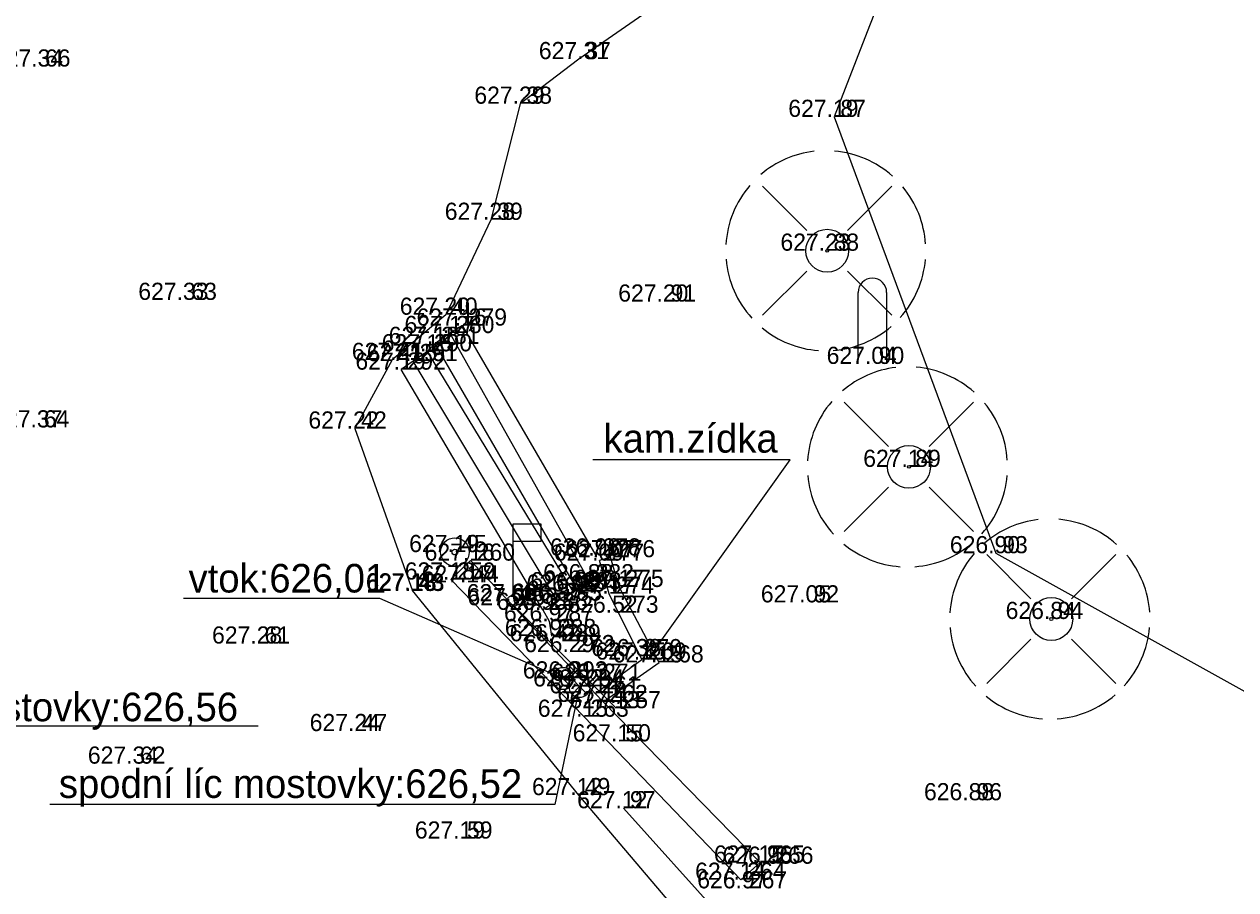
# Model space of a CAD drawing. Extents: x -632073 to -631949, y -1099530 to -1099406.
# Drawn here: x -631995.42 to -631974.23, y -1099492.95 to -1099477.82 of the extents above; entities that cross this region are included whole.
import ezdxf

# ---------------------------------------------------------------- set-up
doc = ezdxf.new("R2010")
doc.units = 0
for name, color, linetype in [('Vrstva 1', 7, 'Continuous'), ('Vrstva 13', 7, 'Continuous'), ('Vrstva 14', 7, 'Continuous'), ('Vrstva 15', 7, 'Continuous'), ('Vrstva 16', 7, 'Continuous'), ('Vrstva 19', 7, 'Continuous'), ('Vrstva 2', 7, 'Continuous'), ('Vrstva 22', 7, 'Continuous'), ('Vrstva 23', 7, 'Continuous'), ('Vrstva 24', 7, 'Continuous'), ('Vrstva 4', 7, 'Continuous'), ('Vrstva 5', 7, 'Continuous'), ('Vrstva 6', 7, 'Continuous'), ('Vrstva 7', 7, 'Continuous'), ('Vrstva 8', 7, 'Continuous'), ('Vrstva 9', 7, 'Continuous')]:
    doc.layers.add(name, color=color, linetype=linetype)

msp = doc.modelspace()

# ---------------------------------------------------------------- linework, layer by layer
at = {"layer": 'Vrstva 1'}
msp.add_line((-631984.94, -1099491.53), (-631981.51, -1099495.34), dxfattribs=at)
at = {"layer": 'Vrstva 13'}
for p, q in [((-631985.72, -1099478.43), (-631985.72, -1099478.43)), ((-631995.17, -1099478.56), (-631995.17, -1099478.56)), ((-631986.75, -1099479.21), (-631986.75, -1099479.21)), ((-631981.26, -1099479.44), (-631981.26, -1099479.44)), ((-631987.26, -1099481.24), (-631987.26, -1099481.24)), ((-631981.38, -1099481.78), (-631981.38, -1099481.78)), ((-631992.61, -1099482.64), (-631992.61, -1099482.64)), ((-631984.23, -1099482.67), (-631984.23, -1099482.67)), ((-631988.05, -1099482.9), (-631988.05, -1099482.9)), ((-631987.76, -1099483.09), (-631987.76, -1099483.09)), ((-631987.98, -1099483.22), (-631987.98, -1099483.22)), ((-631988.24, -1099483.41), (-631988.24, -1099483.41)), ((-631988.99, -1099483.69), (-631988.99, -1099483.69)), ((-631988.62, -1099483.71), (-631988.62, -1099483.71)), ((-631988.37, -1099483.54), (-631988.37, -1099483.54)), ((-631988.83, -1099483.86), (-631988.83, -1099483.86)), ((-631980.59, -1099483.76), (-631980.59, -1099483.76)), ((-631995.19, -1099484.87), (-631995.19, -1099484.87)), ((-631989.64, -1099484.89), (-631989.64, -1099484.89)), ((-631979.95, -1099485.56), (-631979.95, -1099485.56)), ((-631987.89, -1099487.05), (-631987.89, -1099487.05)), ((-631985.42, -1099487.11), (-631985.42, -1099487.11)), ((-631978.43, -1099487.07), (-631978.43, -1099487.07)), ((-631987.62, -1099487.2), (-631987.62, -1099487.2)), ((-631985.36, -1099487.2), (-631985.36, -1099487.2)), ((-631985.17, -1099487.14), (-631985.17, -1099487.14)), ((-631987.96, -1099487.53), (-631987.96, -1099487.53)), ((-631985.54, -1099487.56), (-631985.54, -1099487.56)), ((-631988.64, -1099487.72), (-631988.64, -1099487.72)), ((-631988.63, -1099487.73), (-631988.63, -1099487.73)), ((-631987.68, -1099487.58), (-631987.68, -1099487.58)), ((-631985.82, -1099487.74), (-631985.82, -1099487.74)), ((-631985.76, -1099487.7), (-631985.76, -1099487.7)), ((-631985.02, -1099487.66), (-631985.02, -1099487.66)), ((-631986.88, -1099487.91), (-631986.88, -1099487.91)), ((-631986.87, -1099487.98), (-631986.87, -1099487.98)), ((-631986.1, -1099487.9), (-631986.1, -1099487.9)), ((-631985.19, -1099487.78), (-631985.19, -1099487.78)), ((-631981.73, -1099487.93), (-631981.73, -1099487.93)), ((-631986.35, -1099488.06), (-631986.35, -1099488.06)), ((-631985.11, -1099488.11), (-631985.11, -1099488.11)), ((-631986.24, -1099488.26), (-631986.24, -1099488.26)), ((-631977.46, -1099488.22), (-631977.46, -1099488.22)), ((-631986.2, -1099488.52), (-631986.2, -1099488.52)), ((-631986.12, -1099488.61), (-631986.12, -1099488.61)), ((-631991.33, -1099488.65), (-631991.33, -1099488.65)), ((-631985.88, -1099488.8), (-631985.88, -1099488.8)), ((-631984.7, -1099488.87), (-631984.7, -1099488.87)), ((-631984.62, -1099488.93), (-631984.62, -1099488.93)), ((-631984.32, -1099488.98), (-631984.32, -1099488.98)), ((-631986, -1099489.26), (-631986, -1099489.26)), ((-631985.71, -1099489.4), (-631985.71, -1099489.4)), ((-631985.41, -1099489.3), (-631985.41, -1099489.3)), ((-631985.44, -1099489.52), (-631985.44, -1099489.52)), ((-631985.3, -1099489.67), (-631985.3, -1099489.67)), ((-631985.07, -1099489.78), (-631985.07, -1099489.78)), ((-631985.63, -1099489.93), (-631985.63, -1099489.93)), ((-631989.63, -1099490.18), (-631989.63, -1099490.18)), ((-631985.02, -1099490.36), (-631985.02, -1099490.36)), ((-631993.51, -1099490.75), (-631993.51, -1099490.75)), ((-631985.73, -1099491.3), (-631985.73, -1099491.3)), ((-631984.94, -1099491.53), (-631984.94, -1099491.53)), ((-631978.88, -1099491.39), (-631978.88, -1099491.39)), ((-631987.79, -1099492.06), (-631987.79, -1099492.06)), ((-631982.55, -1099492.48), (-631982.55, -1099492.48)), ((-631982.4, -1099492.5), (-631982.4, -1099492.5)), ((-631982.89, -1099492.78), (-631982.89, -1099492.78)), ((-631982.86, -1099492.93), (-631982.86, -1099492.93))]:
    msp.add_line(p, q, dxfattribs=at)
at = {"layer": 'Vrstva 16'}
for p, q in [((-631981.736, -1099481.425), (-631982.51, -1099480.65)), ((-631981.026, -1099481.425), (-631980.25, -1099480.65)), ((-631981.736, -1099482.135), (-631982.51, -1099482.91)), ((-631981.026, -1099482.135), (-631980.25, -1099482.91)), ((-631980.306, -1099485.205), (-631981.08, -1099484.43)), ((-631979.596, -1099485.205), (-631978.82, -1099484.43)), ((-631980.306, -1099485.915), (-631981.08, -1099486.69)), ((-631979.596, -1099485.915), (-631978.82, -1099486.69)), ((-631977.816, -1099487.865), (-631978.59, -1099487.09)), ((-631977.106, -1099487.865), (-631976.33, -1099487.09)), ((-631977.816, -1099488.575), (-631978.59, -1099489.35)), ((-631977.106, -1099488.575), (-631976.33, -1099489.35))]:
    msp.add_line(p, q, dxfattribs=at)
for centre, radius in [((-631981.38, -1099481.78), 0.375), ((-631981.38, -1099481.78), 0.025), ((-631981.38, -1099481.78), 0.025), ((-631979.95, -1099485.56), 0.375), ((-631979.95, -1099485.56), 0.025), ((-631979.95, -1099485.56), 0.025), ((-631977.46, -1099488.22), 0.375), ((-631977.46, -1099488.22), 0.025), ((-631977.46, -1099488.22), 0.025)]:
    msp.add_circle(centre, radius, dxfattribs=at)
for centre, start, end in [((-631981.405, -1099481.78), 96.7144, 130.447), ((-631981.405, -1099481.78), 48.1897, 84.9117), ((-631981.405, -1099481.78), 139.23, 176.4602), ((-631981.405, -1099481.78), 3.8615, 39.6013), ((-631981.405, -1099481.78), 184.9408, 222.2827), ((-631981.405, -1099481.78), 318.1086, 355.0481), ((-631981.405, -1099481.78), 274.1732, 310.7861), ((-631981.405, -1099481.78), 230.4703, 265.8356), ((-631979.976, -1099485.56), 96.7144, 130.447), ((-631979.976, -1099485.56), 48.1897, 84.9117), ((-631979.976, -1099485.56), 139.23, 176.4602), ((-631979.976, -1099485.56), 3.8615, 39.6013), ((-631979.976, -1099485.56), 184.9408, 222.2827), ((-631979.976, -1099485.56), 318.1086, 355.0481), ((-631977.486, -1099488.22), 96.7144, 130.447), ((-631977.486, -1099488.22), 48.1897, 84.9117), ((-631979.976, -1099485.56), 230.4703, 265.8356), ((-631979.976, -1099485.56), 274.1732, 310.7861), ((-631977.486, -1099488.22), 139.23, 176.4602), ((-631977.486, -1099488.22), 3.8615, 39.6013), ((-631977.486, -1099488.22), 184.9408, 222.2827), ((-631977.486, -1099488.22), 318.1086, 355.0481), ((-631977.486, -1099488.22), 230.4703, 265.8356), ((-631977.486, -1099488.22), 274.1732, 310.7861)]:
    msp.add_arc(centre, 1.75, start, end, dxfattribs=at)
at = {"layer": 'Vrstva 19'}
for p, q in [((-631986.38, -1099486.56), (-631986.88, -1099486.56)), ((-631986.88, -1099486.56), (-631986.88, -1099487.81)), ((-631986.38, -1099486.86), (-631986.38, -1099486.56)), ((-631986.88, -1099486.86), (-631986.38, -1099486.86)), ((-631985.07, -1099489.78), (-631986.87, -1099487.98))]:
    msp.add_line(p, q, dxfattribs=at)
msp.add_circle((-631986.88, -1099487.91), 0.1, dxfattribs=at)
at = {"layer": 'Vrstva 2'}
for p, q in [((-631987.76, -1099483.09), (-631987.98, -1099483.22)), ((-631985.42, -1099487.11), (-631987.76, -1099483.09)), ((-631987.98, -1099483.22), (-631988.24, -1099483.41)), ((-631987.98, -1099483.22), (-631985.54, -1099487.56)), ((-631988.24, -1099483.41), (-631988.37, -1099483.54)), ((-631988.24, -1099483.41), (-631985.76, -1099487.7)), ((-631988.62, -1099483.71), (-631988.83, -1099483.86)), ((-631988.37, -1099483.54), (-631988.62, -1099483.71)), ((-631986.1, -1099487.9), (-631988.62, -1099483.71)), ((-631985.82, -1099487.74), (-631988.37, -1099483.54)), ((-631986.35, -1099488.06), (-631988.83, -1099483.86)), ((-631985.82, -1099487.74), (-631986.1, -1099487.9)), ((-631985.76, -1099487.7), (-631985.82, -1099487.74)), ((-631986.1, -1099487.9), (-631986.35, -1099488.06))]:
    msp.add_line(p, q, dxfattribs=at)
at = {"layer": 'Vrstva 22'}
for p, q in [((-631982.027, -1099485.439), (-631985.476, -1099485.439)), ((-631984.516, -1099488.93), (-631982.027, -1099485.439))]:
    msp.add_line(p, q, dxfattribs=at)
at = {"layer": 'Vrstva 23'}
for p, q in [((-631989.204, -1099487.864), (-631992.635, -1099487.864)), ((-631986, -1099489.26), (-631989.204, -1099487.864)), ((-631985.71, -1099489.4), (-631986.141, -1099491.465)), ((-631999.767, -1099490.089), (-631991.333, -1099490.089)), ((-631986.141, -1099491.465), (-631994.975, -1099491.465))]:
    msp.add_line(p, q, dxfattribs=at)
at = {"layer": 'Vrstva 24'}
for p, q in [((-631980.84, -1099483.76), (-631980.84, -1099482.51)), ((-631980.34, -1099482.51), (-631980.34, -1099483.76))]:
    msp.add_line(p, q, dxfattribs=at)
for radius in [0.25, 0.05]:
    msp.add_circle((-631987.89, -1099487.05), radius, dxfattribs=at)
msp.add_arc((-631980.59, -1099482.51), 0.25, 0, 180, dxfattribs=at)
at = {"layer": 'Vrstva 4'}
msp.add_lwpolyline([(-631980.1, -1099476.46), (-631980.68, -1099477.95), (-631981.26, -1099479.44)], dxfattribs=at)
at = {"layer": 'Vrstva 5'}
for p, q in [((-631981.26, -1099479.44), (-631978.43, -1099487.07)), ((-631978.43, -1099487.07), (-631972.45, -1099490.39))]:
    msp.add_line(p, q, dxfattribs=at)
at = {"layer": 'Vrstva 6'}
for p, q in [((-631986.132, -1099489.128), (-631986, -1099489.26)), ((-631985.868, -1099489.128), (-631986, -1099489.26)), ((-631985.868, -1099489.128), (-631985.868, -1099489.128)), ((-631986, -1099489.26), (-631986.132, -1099489.392)), ((-631986, -1099489.26), (-631985.868, -1099489.392)), ((-631985.842, -1099489.268), (-631985.71, -1099489.4)), ((-631985.71, -1099489.4), (-631985.842, -1099489.532)), ((-631985.578, -1099489.268), (-631985.71, -1099489.4)), ((-631985.71, -1099489.4), (-631985.578, -1099489.532)), ((-631985.578, -1099489.268), (-631985.578, -1099489.268))]:
    msp.add_line(p, q, dxfattribs=at)
for centre, start, end in [((-631986, -1099489.26), 135, 224.9643), ((-631986, -1099489.26), 45, 134.9643), ((-631986, -1099489.26), 315, 44.9643), ((-631985.71, -1099489.4), 45, 134.9643), ((-631986, -1099489.26), 225, 314.9643), ((-631985.71, -1099489.4), 135, 224.9643), ((-631985.71, -1099489.4), 315, 44.9643), ((-631985.71, -1099489.4), 225, 314.9643)]:
    msp.add_arc(centre, 0.188, start, end, dxfattribs=at)
at = {"layer": 'Vrstva 7'}
for p, q in [((-631987.96, -1099487.53), (-631987.62, -1099487.2)), ((-631987.62, -1099487.2), (-631985.44, -1099489.52)), ((-631987.96, -1099487.53), (-631985.63, -1099489.93)), ((-631985.44, -1099489.52), (-631985.3, -1099489.67)), ((-631985.3, -1099489.67), (-631982.55, -1099492.48)), ((-631985.63, -1099489.93), (-631982.89, -1099492.78)), ((-631982.89, -1099492.78), (-631982.55, -1099492.48))]:
    msp.add_line(p, q, dxfattribs=at)
at = {"layer": 'Vrstva 8'}
for p, q in [((-631983.81, -1099477.1), (-631985.72, -1099478.43)), ((-631985.72, -1099478.43), (-631986.75, -1099479.21)), ((-631986.75, -1099479.21), (-631987.26, -1099481.24)), ((-631987.26, -1099481.24), (-631988.05, -1099482.9)), ((-631988.05, -1099482.9), (-631988.99, -1099483.69)), ((-631988.99, -1099483.69), (-631989.64, -1099484.89)), ((-631989.64, -1099484.89), (-631988.63, -1099487.73)), ((-631988.63, -1099487.73), (-631988.64, -1099487.72)), ((-631988.64, -1099487.72), (-631985.73, -1099491.3)), ((-631985.73, -1099491.3), (-631983.33, -1099494.12))]:
    msp.add_line(p, q, dxfattribs=at)
at = {"layer": 'Vrstva 9'}
for p, q in [((-631985.17, -1099487.14), (-631985.36, -1099487.2)), ((-631985.19, -1099487.78), (-631985.36, -1099487.2)), ((-631985.02, -1099487.66), (-631985.17, -1099487.14)), ((-631984.32, -1099488.98), (-631985.02, -1099487.66)), ((-631984.62, -1099488.93), (-631985.19, -1099487.78)), ((-631986.35, -1099488.06), (-631986.24, -1099488.26)), ((-631986.24, -1099488.26), (-631986.2, -1099488.52)), ((-631985.44, -1099489.52), (-631984.62, -1099488.93)), ((-631985.3, -1099489.67), (-631984.32, -1099488.98))]:
    msp.add_line(p, q, dxfattribs=at)

# ---------------------------------------------------------------- texts
at = {"layer": 'Vrstva 14'}
for s, p in [(' 37', (-631985.72, -1099478.43)), (' 66', (-631995.17, -1099478.56)), (' 38', (-631986.75, -1099479.21)), (' 87', (-631981.26, -1099479.44)), (' 39', (-631987.26, -1099481.24)), (' 88', (-631981.38, -1099481.78)), (' 63', (-631992.61, -1099482.64)), (' 91', (-631984.23, -1099482.67)), (' 40', (-631988.05, -1099482.9)), (' 279', (-631987.76, -1099483.09)), (' 281', (-631988.24, -1099483.41)), (' 280', (-631987.98, -1099483.22)), (' 290', (-631988.37, -1099483.54)), (' 41', (-631988.99, -1099483.69)), (' 291', (-631988.62, -1099483.71)), (' 90', (-631980.59, -1099483.76)), (' 292', (-631988.83, -1099483.86)), (' 64', (-631995.19, -1099484.87)), (' 42', (-631989.64, -1099484.89)), (' 89', (-631979.95, -1099485.56)), (' 45', (-631987.89, -1099487.05)), (' 260', (-631987.62, -1099487.2)), (' 278', (-631985.42, -1099487.11)), (' 277', (-631985.36, -1099487.2)), (' 276', (-631985.17, -1099487.14)), (' 93', (-631978.43, -1099487.07)), (' 259', (-631987.96, -1099487.53)), (' 44', (-631987.68, -1099487.58)), (' 282', (-631985.54, -1099487.56)), (' 48', (-631988.64, -1099487.72)), (' 43', (-631988.63, -1099487.73)), (' 284', (-631985.82, -1099487.74)), (' 283', (-631985.76, -1099487.7)), (' 274', (-631985.19, -1099487.78)), (' 275', (-631985.02, -1099487.66)), (' 46', (-631986.88, -1099487.91)), (' 258', (-631986.87, -1099487.98)), (' 286', (-631986.35, -1099488.06)), (' 285', (-631986.1, -1099487.9)), (' 92', (-631981.73, -1099487.93)), (' 287', (-631986.24, -1099488.26)), (' 273', (-631985.11, -1099488.11)), (' 94', (-631977.46, -1099488.22)), (' 61', (-631991.33, -1099488.65)), (' 288', (-631986.2, -1099488.52)), (' 289', (-631986.12, -1099488.61)), (' 272', (-631985.88, -1099488.8)), (' 270', (-631984.7, -1099488.87)), (' 269', (-631984.62, -1099488.93)), (' 268', (-631984.32, -1099488.98)), (' 293', (-631986, -1099489.26)), (' 271', (-631985.41, -1099489.3)), (' 294', (-631985.71, -1099489.4)), (' 261', (-631985.44, -1099489.52)), (' 262', (-631985.3, -1099489.67)), (' 263', (-631985.63, -1099489.93)), (' 257', (-631985.07, -1099489.78)), (' 47', (-631989.63, -1099490.18)), (' 50', (-631985.02, -1099490.36)), (' 62', (-631993.51, -1099490.75)), (' 49', (-631985.73, -1099491.3)), (' 96', (-631978.88, -1099491.39)), (' 97', (-631984.94, -1099491.53)), (' 59', (-631987.79, -1099492.06)), (' 265', (-631982.55, -1099492.48)), (' 266', (-631982.4, -1099492.5)), (' 264', (-631982.89, -1099492.78)), (' 267', (-631982.86, -1099492.93))]:
    msp.add_text(s, height=0.3, dxfattribs=at).set_placement(p)
at = {"layer": 'Vrstva 15'}
for s, p in [('627.31 ', (-631986.422, -1099478.43)), ('627.34 ', (-631995.969, -1099478.56)), ('627.29 ', (-631987.55, -1099479.21)), ('627.19 ', (-631982.06, -1099479.44)), ('627.28 ', (-631988.067, -1099481.24)), ('627.23 ', (-631982.197, -1099481.78)), ('627.33 ', (-631993.427, -1099482.64)), ('627.20 ', (-631985.034, -1099482.67)), ('627.20 ', (-631988.854, -1099482.9)), ('627.16 ', (-631988.56, -1099483.09)), ('627.18 ', (-631989.047, -1099483.41)), ('627.17 ', (-631988.771, -1099483.22)), ('627.16 ', (-631989.17, -1099483.54)), ('627.21 ', (-631989.692, -1099483.69)), ('627.15 ', (-631989.43, -1099483.71)), ('627.04 ', (-631981.389, -1099483.76)), ('627.19 ', (-631989.63, -1099483.86)), ('627.37 ', (-631995.981, -1099484.87)), ('627.22 ', (-631990.452, -1099484.89)), ('627.14 ', (-631980.749, -1099485.56)), ('627.19 ', (-631988.69, -1099487.05)), ('627.16 ', (-631988.42, -1099487.2)), ('626.98 ', (-631986.227, -1099487.11)), ('627.09 ', (-631986.16, -1099487.2)), ('627.07 ', (-631985.962, -1099487.14)), ('626.90 ', (-631979.234, -1099487.07)), ('627.18 ', (-631988.767, -1099487.53)), ('627.17 ', (-631988.471, -1099487.58)), ('626.88 ', (-631986.347, -1099487.56)), ('627.18 ', (-631989.447, -1099487.72)), ('627.18 ', (-631989.437, -1099487.73)), ('626.93 ', (-631986.637, -1099487.74)), ('626.95 ', (-631986.57, -1099487.7)), ('627.17 ', (-631985.981, -1099487.78)), ('627.17 ', (-631985.811, -1099487.66)), ('627.00 ', (-631987.684, -1099487.91)), ('627.09 ', (-631987.67, -1099487.98)), ('626.95 ', (-631987.16, -1099488.06)), ('626.87 ', (-631986.891, -1099487.9)), ('627.05 ', (-631982.54, -1099487.93)), ('626.97 ', (-631987.032, -1099488.26)), ('626.52 ', (-631985.922, -1099488.11)), ('626.84 ', (-631978.259, -1099488.22)), ('627.28 ', (-631992.137, -1099488.65)), ('626.93 ', (-631987.017, -1099488.52)), ('626.42 ', (-631986.933, -1099488.61)), ('626.29 ', (-631986.679, -1099488.8)), ('626.38 ', (-631985.507, -1099488.87)), ('627.15 ', (-631985.43, -1099488.93)), ('627.15 ', (-631985.13, -1099488.98)), ('626.01 ', (-631986.702, -1099489.26)), ('626.27 ', (-631986.202, -1099489.3)), ('626.52 ', (-631986.522, -1099489.4)), ('627.14 ', (-631986.239, -1099489.52)), ('627.14 ', (-631986.099, -1099489.67)), ('627.15 ', (-631986.44, -1099489.93)), ('627.13 ', (-631985.887, -1099489.78)), ('627.24 ', (-631990.429, -1099490.18)), ('627.15 ', (-631985.83, -1099490.36)), ('627.34 ', (-631994.309, -1099490.75)), ('627.12 ', (-631986.542, -1099491.3)), ('626.88 ', (-631979.687, -1099491.39)), ('627.12 ', (-631985.752, -1099491.53)), ('627.19 ', (-631988.59, -1099492.06)), ('627.15 ', (-631983.36, -1099492.48)), ('626.95 ', (-631983.21, -1099492.5)), ('627.14 ', (-631983.689, -1099492.78)), ('626.97 ', (-631983.652, -1099492.93))]:
    msp.add_text(s, height=0.3, dxfattribs=at).set_placement(p)
at = {"layer": 'Vrstva 22'}
msp.add_text('kam.zídka', height=0.5, dxfattribs=at).set_placement((-631985.292, -1099485.311))
at = {"layer": 'Vrstva 23'}
for s, p in [('vtok:626,01', (-631992.548, -1099487.757)), ('spodní líc mostovky:626,56', (-631999.784, -1099490.008)), ('spodní líc mostovky:626,52', (-631994.816, -1099491.349))]:
    msp.add_text(s, height=0.5, dxfattribs=at).set_placement(p)

doc.saveas('drawing.dxf')
